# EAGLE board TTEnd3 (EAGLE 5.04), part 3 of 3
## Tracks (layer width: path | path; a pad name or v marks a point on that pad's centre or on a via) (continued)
N$111 (continued)
  Unten/V1 1.016: 175.01,182.88 R304.1 169.93,182.88 168.66,184.15 G304.2 | 175.01,182.88 177.55,185.42 R303.1 | 175.01,182.88 176.28,181.61 176.28,180.34 178.82,177.8 V307.1
N$112
  Oben/V2 1.016: IC301.3 168.66,165.1 V309.1
N$113
  Oben/V2 1.524: V305.2 167.39,195.58 G301.2
  Unten/V1 1.524: G301.2 168.66,199.39 168.66,205.74 | 168.66,205.74 R311.1 | 168.66,205.74 R312.1
N$114
  Oben/V2 1.524: V305.3 162.31,198.12 G302.1 166.12,201.93 | 166.12,201.93 166.12,212.09 163.58,212.09 | 166.12,201.93 G303.1
  Oben/V2 3.302: 167.39,212.09 163.58,212.09 159.77,215.9 | 159.77,215.9 158.5,217.17 158.5,219.71 | 158.5,219.71 V302.2 | 167.39,212.09 169.93,212.09 | 176.28,217.17 175.01,217.17 172.47,214.63 | 176.28,217.17 178.82,219.71 | 178.82,219.71 V301.2 | 169.93,212.09 183.9,212.09 | 181.36,214.63 182.63,215.9 | 182.63,215.9 178.82,219.71 | 183.9,212.09 181.36,214.63 | 172.47,214.63 178.82,214.63 | 178.82,214.63 181.36,214.63 | 169.93,212.09 172.47,214.63 | 159.77,215.9 162.31,215.9 | 162.31,215.9 163.58,215.9 167.39,212.09 | 178.82,214.63 178.82,219.71 | 162.31,215.9 158.5,219.71 | 176.28,217.17 R302.1 | 182.63,215.9 R301.1 183.9,212.09
N$115
  Oben/V2 1.016: V307.2 R305.1
  Unten/V1 1.016: R305.1 R304.2
N$116  (via drill 0.9 pad 1.5)
  Oben/V2 1.016: G324.2 102.62,177.8 108.97,177.8 110.24,179.07 110.24,191.77 108.97,193.04 | 110.24,198.12 126.75,198.12 129.29,200.66 131.83,200.66 v133.1,201.93 | 110.24,198.12 107.7,198.12 105.16,200.66 V317.1 | 108.97,193.04 R339.1 | 108.97,193.04 110.24,194.31 G321.2 110.24,198.12
  Unten/V1 1.016: T2.A1 G324.2
N$117
  Unten/V1 1.016: R306.2 C302.2 | R306.2 R314.1 | IC301.1 R306.2
N$118
  Oben/V2 2.794: 140.72,222.25 139.45,223.52 139.45,219.71 140.72,219.71 140.72,222.25 | 135.64,227.33 135.89,227.58 137.93,227.58 140.72,224.79 140.72,222.25
  Oben/V2 3.302: 133.1,225.04 128.02,225.04 T302.3 | T302.3 125.48,226.06 | 125.48,226.06 120.4,220.98 122.94,220.98 T302.3 | 133.1,225.04 T302.4 | 133.1,225.04 137.93,225.04 | 137.93,225.04 135.64,227.33 126.75,227.33 125.48,226.06 | 137.93,225.04 139.45,223.52
  Unten/V1 1.524: 136.91,224.79 140.72,220.98 | G312.2 140.72,199.39 C308.2 | G319.1 R321.2
  Unten/V1 2.159: 139.45,208.28 C308.2
  Unten/V1 2.54: 140.72,220.98 V303.3
  Unten/V1 3.302: 130.56,224.79 125.48,224.79 125.48,226.06 T302.3 | 139.45,224.79 136.91,224.79 130.56,224.79 | 130.56,224.79 131.83,226.06 T302.4 | 126.75,227.33 136.91,227.33 139.45,224.79 | 120.4,220.98 V304.3 | 126.75,227.33 T302.3 | 120.4,220.98 126.75,227.33 | 139.45,224.79 140.72,223.52 140.72,220.98 140.72,218.44 139.45,217.17 139.45,208.28 | 120.4,220.98 122.94,220.98 | 122.94,220.98 T302.3 | 120.4,218.44 120.4,214.63 128.02,207.01 131.83,207.01 | 120.4,219.71 120.4,218.44 | 120.4,219.71 120.4,220.98 | G319.1 135.64,209.55 | 135.64,209.55 134.37,209.55 131.83,207.01 | G319.1 136.91,205.74 139.45,208.28 | 131.83,207.01 129.29,207.01 128.02,205.74 125.48,205.74 119.13,212.09 119.13,218.44 120.4,219.71 | 131.83,207.01 133.1,205.74 G319.1 | 135.64,209.55 139.45,209.55 139.45,208.28 | 120.4,218.44 122.94,220.98
N$119  (via drill 3.2 pad 5.99)
  other vias: 107.7,69.85
N$120
  Unten/V1 1.016: R323.2 V312.1
N$121
  Oben/V2 1.016: R324.1 V312.2
  Unten/V1 1.016: G313.1 136.91,157.48 135.64,158.75 R324.1 V311.3
N$122
  Oben/V2 1.016: V313.1 V312.3
N$123
  Oben/V2 1.016: V313.2 125.48,165.1 125.48,163.83 126.75,162.56 R332.1
  Unten/V1 1.016: R332.1 R324.2
N$124
  Oben/V2 1.016: R319.2 148.34,154.94 G313.2 140.72,157.48 V311.2 | V311.2 140.72,162.56 140.72,166.37 138.18,168.91 R322.1 | C310.2 135.64,158.75 136.91,160.02 V311.2
  Unten/V1 1.016: R322.1 C312.1
N$125
  Oben/V2 1.016: R330.2 125.48,180.34 V314.2
  Unten/V1 1.016: R330.2 R329.1
N$126
  Oben/V2 1.016: G311.1 135.64,181.61 139.45,185.42 V306.1
  Unten/V1 1.016: 125.48,182.88 R329.2 129.29,182.88 130.56,184.15 | 125.48,182.88 125.48,184.15 124.21,185.42 R328.2 | V314.1 125.48,182.88 | 130.56,184.15 131.83,182.88 133.61,182.88 135.64,180.85 G311.1 | 130.56,184.15 G314.1
N$127
  Oben/V2 1.524: G319.2 134.37,215.9 138.18,212.09 138.18,200.15 136.91,198.88 136.91,196.85 138.18,195.58 138.18,190.5 G311.2
  Oben/V2 3.302: 115.32,219.71 V304.2 | 135.64,218.44 V303.2 | 135.64,218.44 134.37,218.44 131.83,215.9 R325.2 119.13,215.9 | 119.13,215.9 115.32,219.71 | 135.64,218.44 G319.2 133.1,213.36 131.83,214.63 129.29,214.63 128.02,213.36 117.86,213.36 R326.2 | R326.2 119.13,215.9 | 115.32,219.71 R326.2
  Unten/V1 1.524: G311.2 138.18,185.42 138.18,181.36 139.2,180.34 V306.3
N$128
  Unten/V1 1.524: R327.1 120.4,200.66 130.56,200.66 | 130.56,200.66 130.56,199.39 G310.1 134.37,198.12 143.26,189.23 143.26,184.15 141.99,182.88 V306.2 | 130.56,200.66 R320.1
N$129
  Unten/V1 1.016: R331.1 V315.1
N$130
  Oben/V2 1.016: R333.1 128.02,154.94 G316.2
N$131
  Unten/V1 1.016: V315.2 125.48,158.75 124.21,157.48 | R334.2 124.21,157.48 | G316.1 125.48,156.21 124.21,157.48
N$132
  Oben/V2 1.016: R332.2 124.21,162.56 125.48,161.29 125.48,160.02 R334.1
  Unten/V1 1.016: C313.1 133.1,157.48 R334.1 128.02,156.21 134.37,149.86 G317.1
N$133
  Unten/V1 1.016: C301.1 R303.2
N$134
  Oben/V2 1.016: R328.1 130.56,182.88 131.83,182.88 133.1,184.15 C311.2
N$135
  Oben/V2 1.016: C306.1 166.12,165.1 166.12,162.56 | 166.12,162.56 R316.1 | 166.12,162.56 168.66,162.56 C303.1
  Oben/V2 1.524: C306.1 159.77,173.99 G307.2
  Unten/V1 1.016: R309.1 172.47,160.02 169.93,162.56 | C303.1 168.66,162.56 169.93,162.56 | V310.E 159.77,168.91 C306.1 | R307.1 172.47,165.1 169.93,162.56
N$136
  Oben/V2 1.524: C309.2 143.26,172.72 143.26,186.69 141.99,187.96 G312.1
  Unten/V1 1.016: 133.1,162.56 130.56,165.1 R331.2 | 133.1,162.56 C309.2 | 133.1,160.02 133.1,162.56 | 133.1,160.02 C313.2 | R333.2 133.1,160.02
N$137
  Oben/V2 1.016: V309.3 171.2,172.72 G305.2
N$138
  Unten/V1 1.016: R317.1 V310.C
N$139
  Oben/V2 1.016: R316.2 155.96,160.02 V310.B
  Unten/V1 1.016: R316.2 R315.1
N$141
  Unten/V1 1.016: V313.3 G315.1
N$142  (via drill 0.9 pad 1.5)
  Oben/V2 1.016: G124.2 81.03,180.34 79.76,181.61 79.76,191.77 81.03,193.04 | 81.03,193.04 R139.2 | 81.03,193.04 79.76,194.31 G121.2 79.76,200.66 | 79.76,200.66 V117.1 | 79.76,200.66 60.71,200.66 v59.44,201.93
  Unten/V1 1.016: T1.A1 G124.2
N$143
  Oben/V2 1.016: R109.2 16.26,154.94 G106.1
N$144
  Unten/V1 1.016: V108.2 13.72,158.75 12.45,157.48 | R110.1 12.45,157.48 | 12.45,157.48 13.72,156.21 G106.2
N$145
  Unten/V1 1.016: R107.2 V108.1
N$146
  Oben/V2 1.016: R108.1 12.45,162.56 13.72,161.29 13.72,160.02 R110.2 | C103.2 21.34,160.02 R117.2
  Unten/V1 1.016: 18.8,157.48 18.8,153.67 22.61,149.86 G108.2 | 18.8,157.48 21.34,160.02 C103.2 | 18.8,157.48 R110.2
N$147
  Oben/V2 1.016: V109.2 13.72,165.1 13.72,163.83 14.99,162.56 R108.2 17.53,162.56 18.8,161.29 18.8,158.75 20.07,157.48 23.88,157.48 | 23.88,157.48 C107.1 | 23.88,157.48 R118.1
N$148
  Oben/V2 1.016: V105.1 21.34,198.12 16.26,193.04 G103.2
  Unten/V1 1.016: 14.99,185.42 17.53,182.88 R104.1 | 14.99,185.42 R103.1 11.18,182.88 G104.2 V107.1 | 14.99,185.42 16.26,186.69 G103.2
N$149
  Unten/V1 1.016: V109.1 IC101.3
N$150
  Oben/V2 1.524: V105.2 22.61,195.58 G102.2
  Unten/V1 1.524: R111.1 R112.1 25.15,208.28 22.61,205.74 22.61,200.66 27.69,195.58 V105.2
N$151
  Oben/V2 3.302: 28.96,214.63 31.5,214.63 V102.2 30.23,220.98 30.23,217.17 28.96,215.9 28.96,214.63 | 16.26,212.09 18.8,214.63 25.15,214.63 | 16.26,212.09 6.1,212.09 6.1,213.36 | 11.18,220.47 6.61,215.9 | 6.61,215.9 6.35,215.65 6.1,215.39 6.1,213.36 | 11.18,220.47 V101.2 11.18,219.71 14.99,215.9 | 16.26,212.09 16.26,213.36 11.18,213.36 | 25.15,214.63 28.96,214.63 | 14.99,215.9 23.88,215.9 25.15,214.63 | 25.15,214.63 22.61,212.09 16.26,212.09 | 6.1,213.36 8.64,213.36 | 11.18,213.36 8.64,213.36 | R102.1 14.99,215.9 | 11.18,220.47 11.18,217.17 | 11.18,217.17 11.18,213.36 | 8.64,213.36 8.64,214.63 11.18,217.17 | 6.61,215.9 R101.1
  Unten/V1 1.016: G103.1 23.88,191.77 G101.1
  Unten/V1 1.524: V105.3 G101.1 13.72,204.47 R102.1
N$152
  Unten/V1 1.016: V107.2 R105.1 R104.2
N$153  (via drill 3.2 pad 5.99)
  other vias: 135.64,247.65
N$154
  Unten/V1 1.016: R106.2 R114.1 | IC101.1 21.34,172.72 R106.2 | R106.2 C102.2
N$155
  Unten/V1 1.016: IC305.4 G335.1 G336.1
N$156  (via drill 3.2 pad 5.99)
  other vias: 158.5,247.65
N$157
  Unten/V1 1.016: R123.2 V115.1
N$158
  Unten/V1 1.016: V115.2 56.9,165.1 54.36,162.56 54.36,161.29 53.09,160.02 V111.3 G111.1 R124.1
N$159
  Unten/V1 1.016: V114.1 59.44,168.91 58.17,170.18 V115.3
N$160
  Oben/V2 1.016: R132.1 63.25,162.56 64.52,163.83 64.52,165.1 V114.2
  Unten/V1 1.016: R132.1 60.71,162.56 59.44,161.29 R124.2
N$161
  Oben/V2 1.016: R119.2 41.66,154.94 G111.2 49.28,157.48 | V111.2 49.28,160.02 49.28,157.48 | C110.2 51.82,154.94 49.28,157.48
  Unten/V1 1.016: C112.1 R122.1 56.9,172.72 51.82,167.64 V111.2
N$162
  Unten/V1 1.016: R129.1 R130.2 V112.2
N$163
  Oben/V2 1.016: 59.44,182.88 54.36,182.88 51.82,180.34 V106.1 G113.1 | 59.44,182.88 R129.2 | 59.44,182.88 G114.1
  Unten/V1 1.016: 64.52,182.88 V112.1 | R129.2 64.52,182.88 | 64.52,182.88 64.52,184.15 65.79,185.42 R128.2
N$164
  Oben/V2 1.524: G113.2 V106.3 G113.2 | 59.44,212.09 56.9,209.55 56.9,204.47 53.09,200.66 53.09,194.31 G113.2
  Oben/V2 1.778: G119.2 73.41,218.44
  Oben/V2 3.302: 68.33,214.63 60.71,214.63 | 68.33,214.63 70.87,214.63 | 70.87,214.63 72.14,214.63 | 72.14,214.63 73.41,214.63 | V104.2 73.41,219.71 73.41,218.44 73.41,215.9 72.14,215.9 | 60.71,214.63 V103.2 54.36,218.44 59.44,213.36 59.44,212.09 65.79,212.09 68.33,214.63 | 70.87,214.63 72.14,215.9 | 72.14,214.63 74.68,212.09 75.95,213.36 75.95,219.71 V104.2 | R127.2 V104.2 | R127.2 74.68,213.36 | 72.14,215.9 R127.2 | 68.33,214.63 65.79,217.17 64.52,217.17 | 64.52,217.17 R125.2 | 64.52,217.17 63.25,217.17 60.71,214.63
  Unten/V1 1.778: R127.2 G119.2
  Unten/V1 2.794: V104.2 G119.2
N$165
  Oben/V2 1.524: G112.1 55.63,193.04 53.09,190.5 53.09,185.42 50.55,182.88 V106.2
  Unten/V1 1.524: R126.1 69.6,208.28 67.06,205.74 56.9,205.74 | 56.9,205.74 R120.1 | G112.1 56.9,199.39 56.9,205.74
N$166
  Oben/V2 1.016: R131.1 V113.1
N$167
  Oben/V2 1.016: R133.1 61.98,154.94 G116.2
N$168
  Unten/V1 1.016: V113.2 64.52,165.1 64.52,158.75 65.79,157.48 | 65.79,157.48 R134.2 | G116.1 64.52,156.21 65.79,157.48
N$169
  Oben/V2 1.016: C113.1 56.9,160.02 59.44,160.02 R134.1 64.52,160.02 64.52,161.29 65.79,162.56 R132.2
  Unten/V1 1.016: G117.1 55.63,149.86 61.98,156.21 R134.1
N$170
  Unten/V1 1.016: R103.2 C101.1
N$171
  Unten/V1 1.016: C111.2 R128.1
N$172
  Oben/V2 1.016: C106.1 27.69,171.45 26.42,170.18 26.42,167.64 23.88,165.1 23.88,162.56 | 23.88,162.56 R116.1 | C103.1 21.34,162.56 23.88,162.56
  Oben/V2 1.524: C106.1 G107.2
  Unten/V1 1.016: R109.1 17.53,160.02 20.07,162.56 | 20.07,162.56 21.34,162.56 C103.1 | C106.1 30.23,170.18 34.04,166.37 V110.E | R107.1 17.53,165.1 20.07,162.56
N$173
  Oben/V2 1.016: R133.2 59.44,162.56 56.9,162.56 | C113.2 56.9,162.56 | C109.2 51.82,167.64 51.82,165.1 54.36,162.56 56.9,162.56
  Unten/V1 1.016: R131.2 59.69,165.1 C113.2
  Unten/V1 1.524: C109.2 46.74,172.72 51.82,177.8 51.82,186.69 G110.1
N$174
  Oben/V2 1.016: V109.3 18.8,172.72 G105.2
N$175
  Unten/V1 1.016: R117.1 V110.C
N$176
  Oben/V2 1.016: R116.2 V110.B
  Unten/V1 1.016: R116.2 R115.1
N$177  (via drill 0.9 pad 1.5)
  Unten/V1 1.016: R115.2 26.42,171.45 28.96,173.99 28.96,179.07 23.88,184.15 23.88,185.42 21.34,187.96 20.07,187.96 2.29,205.74 2.29,227.33 27.69,252.73 41.66,252.73 EIN1.1 44.2,252.73 98.81,252.73 | R315.2 163.58,171.45 161.04,173.99 161.04,179.07 166.12,184.15 166.12,187.96 187.71,209.55 187.71,227.33 162.31,252.73 98.81,252.73 | 98.81,252.73 v98.81,247.65
N$178
  Oben/V2 1.016: G115.1 58.17,172.72 60.71,170.18 V114.3
N$179
  Oben/V2 1.016: R380.1 148.34,66.04 P301.2
  Unten/V1 1.016: P301.2 P301.S
N$180
  Unten/V1 1.016: T2.A2 G324.1 103.13,180.34 101.86,181.61 101.86,184.4 102.62,185.17 102.62,187.96 100.08,190.5 V319.1 R338.1 R337.1
N$181
  Unten/V1 1.524: G328.2 G326.2 171.2,54.61 169.93,53.34 V322.2
N$182
  Oben/V2 1.016: R434.2 97.54,31.75 96.27,33.02 96.27,55.88 97.54,57.15 97.54,92.71 96.27,93.98 96.27,100.33 97.54,101.6 97.54,180.59 98.81,181.86 98.81,182.88 | 98.81,182.88 C332.1 | 98.81,182.88 J305.1
  Unten/V1 1.016: C332.1 98.56,183.9 G323.1
N$183
  Oben/V2 1.016: R335.2 111.51,205.74 112.78,204.47 112.78,201.93 111.51,200.66 V317.3
N$184
  Oben/V2 1.016: V116.2 89.92,208.28 G120.2
  Unten/V1 1.016: G123.2 83.57,185.42 84.84,186.69 84.84,187.96 R140.1 R139.1 89.92,195.58 89.92,203.2 V116.2
N$185
  Unten/V1 1.016: R389.2 131.83,7.62 130.56,8.89 R399.2 R400.1
N$186
  Unten/V1 1.016: R341.2 106.43,137.16 100.08,143.51 J306.2 T2.14
N$187
  Oben/V2 1.016: V127.1 39.12,55.12 35.82,58.42 25.15,58.42 23.88,57.15 23.88,52.07 22.61,50.8 V122.1 20.07,50.8 16.26,46.99 16.26,41.91 20.07,38.1 V123.2
  Unten/V1 1.016: 41.66,58.42 41.66,64.77 R179.1 | 41.66,58.42 R182.1 | 41.66,58.42 39.12,55.88 V127.1
N$188
  Unten/V1 1.016: R141.2 J106.2 87.38,147.32 83.26,151.44 T1.14
N$189
  Oben/V2 1.016: V117.3 R135.1
N$190
  Unten/V1 1.016: T1.A2 G124.1 88.65,181.61 88.65,184.15 87.38,185.42 87.38,187.96 V119.1 89.92,193.04 R138.1 R137.1
N$191
  Oben/V2 1.524: R312.2 157.23,205.74 155.96,207.01 155.96,214.63 153.42,217.17 153.42,220.98 V302.1
N$192
  Oben/V2 1.524: V301.1 172.47,220.98 168.66,217.17 R311.2
  Unten/V1 1.524: R311.2 173.74,220.98
N$193
  Unten/V1 1.524: V303.1 129.29,220.98 129.29,212.09 R320.2
N$194
  Oben/V2 1.524: V304.1 110.24,220.98 R327.2
  Unten/V1 1.524: R327.2 110.24,220.98
N$195
  Oben/V2 1.524: V102.1 26.42,220.98 R111.2
  Unten/V1 1.524: R111.2 26.42,220.98
N$196
  Oben/V2 1.524: V103.1 49.28,220.98 49.28,218.44 R120.2
  Unten/V1 1.524: R120.2 49.28,218.44 49.28,220.98
N$197
  Oben/V2 1.524: R126.2 69.6,220.98
  Unten/V1 1.524: R126.2 69.6,220.98 V104.1
N$198
  Oben/V2 1.524: V101.1 6.1,220.98 2.29,217.17 2.29,210.82 4.83,208.28 R112.2
N$199  (via drill 3.2 pad 5.99)
  other vias: 178.82,247.65
N$200
  Unten/V1 1.016: R336.1 R337.2 V318.3
N$201
  Unten/V1 1.524: R321.1 131.83,189.23 G310.2
N$202
  Unten/V1 1.524: R121.1 58.17,190.5 G112.2
N$203
  Unten/V1 1.524: G102.1 18.8,204.47 R113.2
N$204
  Oben/V2 1.016: R181.1 42.93,60.96 40.39,63.5 R168.1
  Unten/V1 1.016: 41.66,71.12 39.12,71.12 36.58,68.58 36.58,64.77 37.85,63.5 R168.1 36.58,60.96 36.58,58.42 34.04,55.88 V127.3 | 41.66,71.12 R178.1 | 41.66,71.12 P101.1
N$205
  Unten/V1 1.016: R179.2 R180.2 51.82,63.5 | V129.3 54.36,54.61 56.9,57.15 56.9,60.96 R191.1 51.82,63.5 | R182.2 50.55,58.42 51.82,59.69 51.82,63.5
N$206
  Oben/V2 1.016: V319.2 100.08,195.58 R338.2 105.16,193.04 V318.1
N$208
  Unten/V1 1.016: V316.1 R335.1 102.62,203.2 107.7,198.12 V318.2 105.16,190.5 G322.2
N$209
  Unten/V1 1.016: G122.2 84.84,190.5 84.84,195.58 V118.2 87.38,203.2 R135.2 V116.1
N$210
  Oben/V2 1.016: V316.2 102.62,203.2 105.16,205.74 G320.2
  Unten/V1 1.016: G323.2 R340.1 R339.2 100.08,195.58 V316.2
N$211  (via drill 0.9 pad 1.5)
  Unten/V1 1.016: G121.1 V117.2 89.92,210.82 v98.81,210.82 100.08,210.82 V317.2 G321.1
N$214
  Unten/V1 1.016: G139.2 G138.2 IC105.8
N$215
  Unten/V1 1.016: G339.1 J4.1 G139.1
N$216
  Oben/V2 0.508: G338.2 112.78,22.86
  Oben/V2 1.016: IC305.8 120.4,21.59 119.13,22.86 112.78,22.86
  Unten/V1 1.016: G339.2 G338.2
N$217  (via drill 0.9 pad 1.5)
  Oben/V2 1.524: C105.1 31.5,187.96 28.96,185.42 G107.1
  Oben/V2 2.794: 17.53,220.98 16.26,220.98
  Oben/V2 3.302: T101.3 T101.4 13.72,224.79 16.26,222.25 | T101.3 16.26,226.06 16.26,222.25 | 16.26,222.25 16.26,220.98 | T101.3 18.8,222.25 17.53,220.98
  Unten/V1 1.524: C105.1 28.96,205.74 | 28.96,205.74 R113.1 26.42,204.47 G101.2 | 22.61,217.17 23.88,217.17 25.15,215.9 27.69,215.9 28.96,217.17 30.23,217.17 | 28.96,205.74 v28.96,201.93
  Unten/V1 2.159: 36.33,220.98 V102.3
  Unten/V1 2.54: 21.34,217.17 18.8,219.71 T101.3
  Unten/V1 2.794: 34.04,217.17 31.5,217.17 | 31.5,217.17 30.23,217.17 | 31.5,217.17 31.5,212.09
  Unten/V1 3.302: T101.3 T101.4 | T101.3 T101.4 | 16.26,220.98 V101.3 | 18.8,217.17 18.8,214.63 28.96,214.63 31.5,212.09 | 18.8,217.17 16.26,219.71 16.26,220.98 | 36.33,220.98 36.33,219.96 | 36.33,219.96 36.33,219.46 34.04,217.17 34.04,214.63 | 34.04,214.63 31.5,212.09 | 31.5,212.09 C105.1 | 16.26,220.98 16.26,226.06 T101.3 | T101.3 T101.4 | T101.3 20.07,226.06 20.07,219.71 22.61,217.17 21.34,217.17 18.8,217.17 | 34.04,214.63 34.04,214.88 36.33,217.17 36.33,219.96
N$218
  Oben/V2 1.016: R180.1 41.66,66.04 P101.2
  Unten/V1 1.016: P101.2 P101.S
N$219
  Oben/V2 1.016: R228.2 75.95,43.18 77.22,44.45 77.22,46.99 73.41,50.8 V136.3
N$220
  Oben/V2 1.524: V122.2 20.07,53.34 18.8,54.61 G126.2
  Unten/V1 1.524: G126.2 G129.2
N$221
  Unten/V1 1.524: G129.1 R164.2
N$222
  Oben/V2 1.016: G104.1 11.18,180.34 13.72,177.8 C102.1 17.53,177.8 18.8,176.53 18.8,175.26 G105.1
  Unten/V1 1.016: V108.3 G105.1
N$223
  Unten/V1 1.016: V113.3 64.52,170.18 G115.2 60.71,172.72 59.44,173.99 59.44,176.53 60.71,177.8 | 60.71,177.8 C112.2 | G114.2 59.44,179.07 60.71,177.8
N$224
  Oben/V2 1.016: R367.1 172.47,43.18 173.74,44.45 173.74,46.99 169.93,50.8 V322.3
N$225
  Unten/V1 1.524: G332.2 R425.1
N$226
  Oben/V2 1.524: V336.2 116.59,53.34 115.32,54.61 G333.1
  Unten/V1 1.524: G333.1 G332.1
N$227
  Unten/V1 1.016: V331.3 R424.1
N$228
  Unten/V1 1.016: V331.1 V332.3 122.94,48.26 120.4,45.72 R427.2 G334.1
N$229
  Unten/V1 1.016: R428.2 114.05,43.18 112.78,44.45 112.78,52.07 116.59,55.88 V336.3
N$230
  Oben/V2 1.016: G304.1 171.2,175.26 | 171.2,175.26 173.74,177.8 C302.1 | 171.2,175.26 G305.1
  Unten/V1 1.016: G305.1 V308.3
N$231
  Unten/V1 1.016: G315.2 124.21,172.72 125.48,171.45 | 125.48,171.45 V315.3 | 125.48,171.45 126.75,172.72 128.02,172.72 130.56,175.26 G314.2 C312.2
N$530
  Unten/V1 1.016: R307.2 V308.1
N$720  (via drill 0.9 pad 1.5, 3.2 pad 5.99)
  Oben/V2 2.54: v11.18,128.27 v11.18,139.7
N$1330  (via drill 3.2 pad 5.99)
  other vias: 11.18,69.85
N$14400  (via drill 3.2 pad 5.99)
  other vias: 178.82,69.85
N$14500  (via drill 3.2 pad 5.99)
  other vias: 107.7,128.27
N$17900  (via drill 0.9 pad 1.5, 3.2 pad 5.99)
  Oben/V2 2.54: v178.82,128.27 v178.82,139.7
OFFSET1
  Unten/V1 1.016: R232.1 IC105.7 74.68,21.59 78.49,25.4 81.03,25.4 84.84,29.21 MP15.1 R234.1
OFFSET2
  Unten/V1 1.016: R431.1 IC305.7 117.86,21.34 113.8,25.4 108.97,25.4 105.16,29.21 MP16.1 R434.1

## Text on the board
Oben/V2: Weiten 09 | Endverstärker/ | Netzgerät
Unten/V1: Weiten 09 | Endverstärker/ | Netzgerät
Namen/obe: Ein/Aus | Eingang- | GND | Eingang+ | B | C | E | B | C | E | B | C | E | B | C | E | B | C | E | B | C | E | B | C | E | B | C | E | +UB1 | MASSE | Masse | -UB1 | -UB2 | +UB2 | -LED | +LED | -LED | +LED | B | C | E | B | C | E | B | C | E | B | C | E | E | C | B | E | C | B | E | C | B | E | C | B | -TT | -TT | +TT | +TT | 2xBassendstufe | Ruhestrom | Ruhestrom | B | E | E | B | B | E | E | B | -15V | +15V | NF-Eingang | NF-Eingang
Bemaáung: 190 | 12,7 | 144,5 | 12,7 | 32,8 | Kupferauflage 70µm | 6 | 254 | 195,6 | 182,9 | 185,2 | 153,4 | 56,9 | 36,6 | 4,8 | 6 | 53,3 | 43,2 | 38,1 | 3,2 | 22 | 5 | 5 | 5 | 82,3 | 95 | 107,7 | 178,82 | 185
